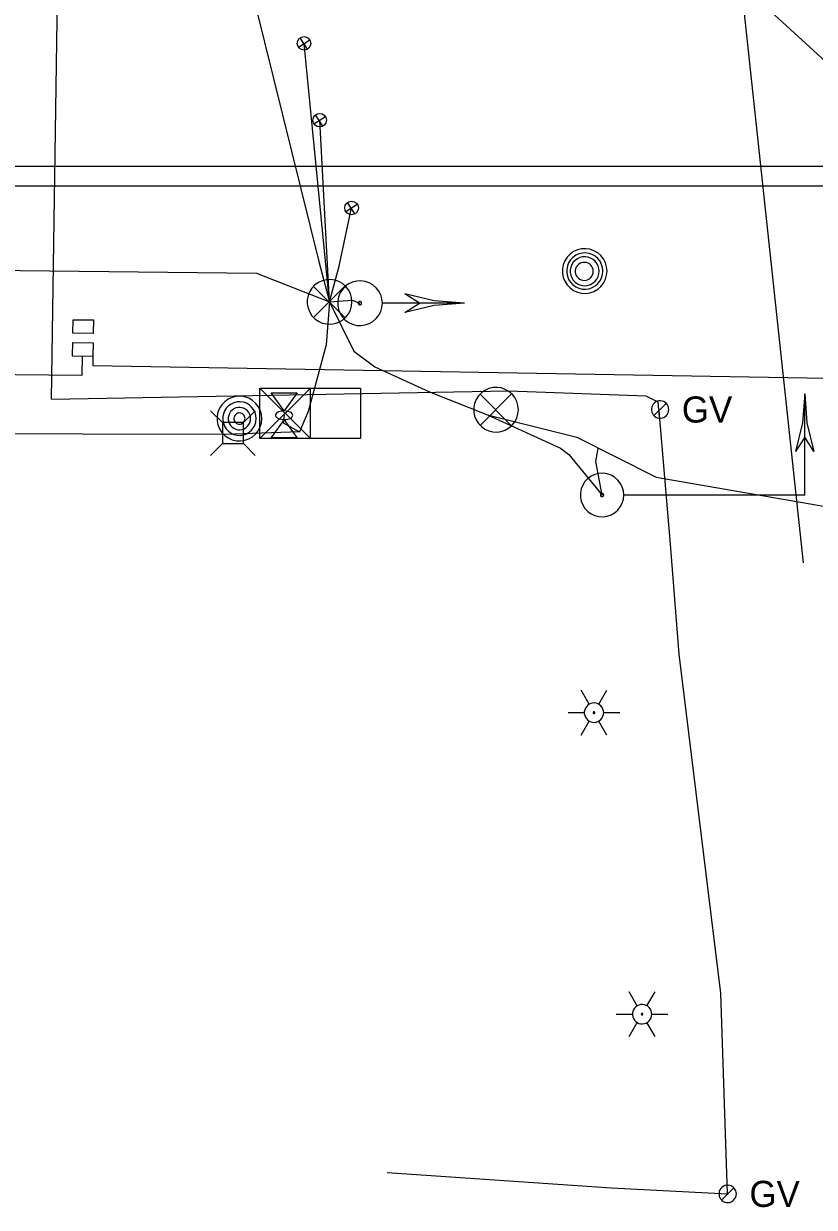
# Model space of a CAD drawing. Extents: x 596028 to 606371, y 330010 to 403088.
# Drawn here: x 604942.5 to 605059.1, y 349725.2 to 349899.9 of the extents above; entities that cross this region are included whole.
import ezdxf

# ---------------------------------------------------------------- set-up
doc = ezdxf.new("R2010")
doc.units = 0
for name, color, linetype in [('E_LTG', 7, 'Continuous'), ('E_SIG', 7, 'Continuous'), ('E_SIG_Conduit', 7, 'Continuous'), ('E_UTL_E', 7, 'Continuous'), ('E_UTL_E_Bold', 7, 'Continuous'), ('E_UTL_E_UG', 7, 'Continuous'), ('E_UTL_FO_UG', 7, 'Continuous'), ('E_UTL_G', 7, 'Continuous'), ('E_UTL_G_UG', 7, 'Continuous'), ('E_UTL_Loop_UG', 7, 'Continuous'), ('E_UTL_MH', 7, 'Continuous'), ('E_UTL_Overhead', 7, 'Continuous'), ('E_UTL_T_UG', 7, 'Continuous')]:
    doc.layers.add(name, color=color, linetype=linetype)

# ---------------------------------------------------------------- blocks, each defined once
blk = doc.blocks.new('_U336')
at = {"layer": 'E_SIG'}
for p, q in [((-6.1, 0.4), (6.1, 0.4)), ((0, 6.1), (0, -6.1))]:
    blk.add_line(p, q, dxfattribs=at)
blk.add_circle((0, 0), 6.1, dxfattribs=at)
blk = doc.blocks.new('_U337')
at = {"layer": 'E_SIG'}
for p, q in [((-6.1, 0.4), (6.1, 0.4)), ((0, 6.1), (0, -6.1))]:
    blk.add_line(p, q, dxfattribs=at)
blk.add_circle((0, 0), 6.1, dxfattribs=at)
blk = doc.blocks.new('_U338')
at = {"layer": 'E_SIG'}
for p, q in [((-6.1, 0.4), (6.1, 0.4)), ((0, 6.1), (0, -6.1))]:
    blk.add_line(p, q, dxfattribs=at)
blk.add_circle((0, 0), 6.1, dxfattribs=at)
blk = doc.blocks.new('ACAD_PROXY_ENTITY_15')
at = {"layer": 'E_LTG'}
for points in [[(1843663.8, 1030159.59), (1843660.17, 1030165.87)], [(1843668.16, 1030159.59), (1843671.79, 1030165.87)], [(1843654.37, 1030155.82), (1843661.62, 1030155.82)], [(1843670.34, 1030155.82), (1843670.26, 1030156.64), (1843670.02, 1030157.44), (1843669.64, 1030158.17), (1843669.13, 1030158.82), (1843668.51, 1030159.36), (1843667.79, 1030159.78), (1843667.01, 1030160.05), (1843666.19, 1030160.17), (1843665.36, 1030160.13), (1843664.56, 1030159.93), (1843663.8, 1030159.59), (1843663.13, 1030159.11), (1843662.56, 1030158.51), (1843662.11, 1030157.81), (1843661.8, 1030157.04), (1843661.64, 1030156.23), (1843661.64, 1030155.4), (1843661.8, 1030154.59), (1843662.11, 1030153.82), (1843662.56, 1030153.12), (1843663.13, 1030152.52), (1843663.8, 1030152.04), (1843664.56, 1030151.7), (1843665.36, 1030151.51), (1843666.19, 1030151.47), (1843667.01, 1030151.58), (1843667.79, 1030151.85), (1843668.51, 1030152.27), (1843669.13, 1030152.81), (1843669.64, 1030153.46), (1843670.02, 1030154.2), (1843670.26, 1030154.99), (1843670.34, 1030155.82)], [(1843670.34, 1030155.82), (1843670.26, 1030156.64), (1843670.02, 1030157.44), (1843669.64, 1030158.17), (1843669.13, 1030158.82), (1843668.51, 1030159.36), (1843667.79, 1030159.78), (1843667.01, 1030160.05), (1843666.19, 1030160.17), (1843665.36, 1030160.13), (1843664.56, 1030159.93), (1843663.8, 1030159.59), (1843663.13, 1030159.11), (1843662.56, 1030158.51), (1843662.11, 1030157.81), (1843661.8, 1030157.04), (1843661.64, 1030156.23), (1843661.64, 1030155.4), (1843661.8, 1030154.59), (1843662.11, 1030153.82), (1843662.56, 1030153.12), (1843663.13, 1030152.52), (1843663.8, 1030152.04), (1843664.56, 1030151.7), (1843665.36, 1030151.51), (1843666.19, 1030151.47), (1843667.01, 1030151.58), (1843667.79, 1030151.85), (1843668.51, 1030152.27), (1843669.13, 1030152.81), (1843669.64, 1030153.46), (1843670.02, 1030154.2), (1843670.26, 1030154.99), (1843670.34, 1030155.82)], [(1843670.34, 1030155.82), (1843670.26, 1030156.64), (1843670.02, 1030157.44), (1843669.64, 1030158.17), (1843669.13, 1030158.82), (1843668.51, 1030159.36), (1843667.79, 1030159.78), (1843667.01, 1030160.05), (1843666.19, 1030160.17), (1843665.36, 1030160.13), (1843664.56, 1030159.93), (1843663.8, 1030159.59), (1843663.13, 1030159.11), (1843662.56, 1030158.51), (1843662.11, 1030157.81), (1843661.8, 1030157.04), (1843661.64, 1030156.23), (1843661.64, 1030155.4), (1843661.8, 1030154.59), (1843662.11, 1030153.82), (1843662.56, 1030153.12), (1843663.13, 1030152.52), (1843663.8, 1030152.04), (1843664.56, 1030151.7), (1843665.36, 1030151.51), (1843666.19, 1030151.47), (1843667.01, 1030151.58), (1843667.79, 1030151.85), (1843668.51, 1030152.27), (1843669.13, 1030152.81), (1843669.64, 1030153.46), (1843670.02, 1030154.2), (1843670.26, 1030154.99), (1843670.34, 1030155.82)], [(1843666.34, 1030155.82), (1843666.34, 1030155.88), (1843666.32, 1030155.95), (1843666.29, 1030156.01), (1843666.24, 1030156.07), (1843666.19, 1030156.11), (1843666.13, 1030156.15), (1843666.07, 1030156.17), (1843666, 1030156.18), (1843665.93, 1030156.18), (1843665.86, 1030156.16), (1843665.8, 1030156.13), (1843665.74, 1030156.09), (1843665.69, 1030156.04), (1843665.66, 1030155.98), (1843665.63, 1030155.92), (1843665.62, 1030155.85), (1843665.62, 1030155.78), (1843665.63, 1030155.71), (1843665.66, 1030155.65), (1843665.69, 1030155.59), (1843665.74, 1030155.54), (1843665.8, 1030155.5), (1843665.86, 1030155.47), (1843665.93, 1030155.46), (1843666, 1030155.45), (1843666.07, 1030155.46), (1843666.13, 1030155.49), (1843666.19, 1030155.52), (1843666.24, 1030155.57), (1843666.29, 1030155.62), (1843666.32, 1030155.68), (1843666.34, 1030155.75), (1843666.34, 1030155.82)], [(1843670.34, 1030155.82), (1843677.59, 1030155.82)], [(1843660.17, 1030145.76), (1843663.8, 1030152.04)], [(1843671.79, 1030145.76), (1843668.16, 1030152.04)]]:
    blk.add_lwpolyline(points, dxfattribs=at)

msp = doc.modelspace()

# ---------------------------------------------------------------- linework, layer by layer
at = {"layer": 'E_SIG'}
for points in [[(604990.87, 349858.81), (604990.81, 349859.44), (604990.64, 349860.04), (604990.35, 349860.6), (604989.96, 349861.09), (604989.49, 349861.5), (604988.94, 349861.81), (604988.35, 349862.02), (604987.73, 349862.11), (604987.1, 349862.08), (604986.49, 349861.93), (604985.92, 349861.67), (604985.41, 349861.31), (604984.98, 349860.85), (604984.64, 349860.32), (604984.41, 349859.74), (604984.29, 349859.13), (604984.29, 349858.5), (604984.41, 349857.88), (604984.64, 349857.3), (604984.98, 349856.77), (604985.41, 349856.32), (604985.92, 349855.95), (604986.49, 349855.69), (604987.1, 349855.55), (604987.73, 349855.52), (604988.35, 349855.61), (604988.94, 349855.81), (604989.49, 349856.12), (604989.96, 349856.54), (604990.35, 349857.03), (604990.64, 349857.59), (604990.81, 349858.19), (604990.87, 349858.81)], [(604989.83, 349861.15), (604985.22, 349856.49)], [(604985.22, 349861.1), (604989.88, 349856.45)], [(604995.36, 349858.62), (604995.3, 349859.24), (604995.12, 349859.85), (604994.83, 349860.4), (604994.44, 349860.9), (604993.97, 349861.31), (604993.43, 349861.62), (604992.83, 349861.83), (604992.21, 349861.92), (604991.59, 349861.89), (604990.98, 349861.74), (604990.41, 349861.48), (604989.89, 349861.11), (604989.46, 349860.66), (604989.12, 349860.13), (604988.89, 349859.55), (604988.77, 349858.93), (604988.77, 349858.31), (604988.89, 349857.69), (604989.12, 349857.11), (604989.46, 349856.58), (604989.89, 349856.13), (604990.41, 349855.76), (604990.98, 349855.5), (604991.59, 349855.35), (604992.21, 349855.32), (604992.83, 349855.41), (604993.43, 349855.62), (604993.97, 349855.93), (604994.44, 349856.34), (604994.83, 349856.84), (604995.12, 349857.39), (604995.3, 349858), (604995.36, 349858.62)], [(604992.31, 349858.62), (604992.3, 349858.67), (604992.29, 349858.71), (604992.27, 349858.76), (604992.24, 349858.79), (604992.2, 349858.83), (604992.16, 349858.85), (604992.12, 349858.87), (604992.07, 349858.87), (604992.02, 349858.87), (604991.97, 349858.86), (604991.93, 349858.84), (604991.89, 349858.81), (604991.86, 349858.78), (604991.83, 349858.74), (604991.81, 349858.69), (604991.8, 349858.64), (604991.8, 349858.6), (604991.81, 349858.55), (604991.83, 349858.5), (604991.86, 349858.46), (604991.89, 349858.43), (604991.93, 349858.4), (604991.97, 349858.38), (604992.02, 349858.37), (604992.07, 349858.37), (604992.12, 349858.37), (604992.16, 349858.39), (604992.2, 349858.41), (604992.24, 349858.45), (604992.27, 349858.48), (604992.29, 349858.53), (604992.3, 349858.57), (604992.31, 349858.62)], [(605000.86, 349858.62), (604998.66, 349860)], [(605007.46, 349858.62), (605003, 349858.97), (604998.66, 349859.99)], [(605007.46, 349858.62), (604995.41, 349858.62)], [(605007.46, 349858.62), (605003, 349858.27), (604998.66, 349857.24)], [(604998.66, 349857.25), (605000.86, 349858.62)], [(604977.58, 349841.6), (604977.52, 349842.22), (604977.34, 349842.82), (604977.06, 349843.38), (604976.67, 349843.87), (604976.19, 349844.28), (604975.65, 349844.6), (604975.06, 349844.8), (604974.44, 349844.89), (604973.81, 349844.86), (604973.2, 349844.71), (604972.63, 349844.45), (604972.12, 349844.09), (604971.69, 349843.64), (604971.35, 349843.11), (604971.11, 349842.53), (604970.99, 349841.91), (604970.99, 349841.28), (604971.11, 349840.67), (604971.35, 349840.08), (604971.69, 349839.56), (604972.12, 349839.1), (604972.63, 349838.74), (604973.2, 349838.48), (604973.81, 349838.33), (604974.44, 349838.3), (604975.06, 349838.39), (604975.65, 349838.59), (604976.19, 349838.91), (604976.67, 349839.32), (604977.06, 349839.81), (604977.34, 349840.37), (604977.52, 349840.97), (604977.58, 349841.6)], [(604977.31, 349838.66), (604977.31, 349846.09)], [(604977.31, 349846.09), (604992.16, 349846.09)], [(604984.74, 349846.09), (604977.31, 349838.66)], [(604977.31, 349846.09), (604984.74, 349838.66)], [(604984.74, 349838.66), (604984.74, 349846.09)], [(604992.16, 349846.09), (604992.16, 349838.66)], [(605015.43, 349842.9), (605015.37, 349843.53), (605015.19, 349844.13), (605014.91, 349844.69), (605014.52, 349845.18), (605014.04, 349845.59), (605013.5, 349845.91), (605012.91, 349846.11), (605012.29, 349846.2), (605011.66, 349846.17), (605011.05, 349846.02), (605010.48, 349845.76), (605009.97, 349845.4), (605009.53, 349844.94), (605009.2, 349844.42), (605008.96, 349843.83), (605008.84, 349843.22), (605008.84, 349842.59), (605008.96, 349841.97), (605009.2, 349841.39), (605009.53, 349840.86), (605009.97, 349840.41), (605010.48, 349840.05), (605011.05, 349839.79), (605011.66, 349839.64), (605012.29, 349839.61), (605012.91, 349839.7), (605013.5, 349839.9), (605014.04, 349840.22), (605014.52, 349840.63), (605014.91, 349841.12), (605015.19, 349841.68), (605015.37, 349842.28), (605015.43, 349842.9)], [(605014.39, 349845.24), (605009.78, 349840.58)], [(605009.78, 349845.19), (605014.43, 349840.54)], [(605057.66, 349845.27), (605057.33, 349840.95), (605056.33, 349836.73)], [(605057.66, 349830.32), (605057.66, 349845.27)], [(605057.66, 349845.27), (605058, 349840.95), (605059, 349836.73)], [(604976.75, 349841.6), (604976.71, 349842.06), (604976.58, 349842.52), (604976.36, 349842.93), (604976.07, 349843.3), (604975.72, 349843.61), (604975.31, 349843.85), (604974.86, 349844), (604974.4, 349844.07), (604973.93, 349844.05), (604973.47, 349843.94), (604973.04, 349843.74), (604972.66, 349843.47), (604972.33, 349843.13), (604972.08, 349842.73), (604971.91, 349842.29), (604971.82, 349841.83), (604971.82, 349841.36), (604971.91, 349840.9), (604972.08, 349840.46), (604972.33, 349840.07), (604972.66, 349839.73), (604973.04, 349839.45), (604973.47, 349839.26), (604973.93, 349839.15), (604974.4, 349839.12), (604974.86, 349839.19), (604975.31, 349839.34), (604975.72, 349839.58), (604976.07, 349839.89), (604976.36, 349840.26), (604976.58, 349840.68), (604976.71, 349841.13), (604976.75, 349841.6)], [(604975.93, 349841.6), (604975.9, 349841.91), (604975.81, 349842.21), (604975.67, 349842.49), (604975.47, 349842.73), (604975.24, 349842.94), (604974.97, 349843.1), (604974.67, 349843.2), (604974.36, 349843.24), (604974.05, 349843.23), (604973.74, 349843.16), (604973.45, 349843.03), (604973.2, 349842.84), (604972.98, 349842.62), (604972.81, 349842.35), (604972.7, 349842.06), (604972.64, 349841.75), (604972.64, 349841.44), (604972.7, 349841.13), (604972.81, 349840.84), (604972.98, 349840.58), (604973.2, 349840.35), (604973.45, 349840.17), (604973.74, 349840.04), (604974.05, 349839.96), (604974.36, 349839.95), (604974.67, 349839.99), (604974.97, 349840.1), (604975.24, 349840.25), (604975.47, 349840.46), (604975.67, 349840.7), (604975.81, 349840.98), (604975.9, 349841.28), (604975.93, 349841.6)], [(604975.1, 349841.6), (604975.09, 349841.75), (604975.05, 349841.9), (604974.97, 349842.04), (604974.88, 349842.17), (604974.76, 349842.27), (604974.62, 349842.35), (604974.47, 349842.4), (604974.32, 349842.42), (604974.16, 349842.41), (604974.01, 349842.38), (604973.87, 349842.31), (604973.74, 349842.22), (604973.63, 349842.11), (604973.55, 349841.97), (604973.49, 349841.83), (604973.46, 349841.67), (604973.46, 349841.52), (604973.49, 349841.36), (604973.55, 349841.22), (604973.63, 349841.09), (604973.74, 349840.97), (604973.87, 349840.88), (604974.01, 349840.82), (604974.16, 349840.78), (604974.32, 349840.77), (604974.47, 349840.79), (604974.62, 349840.85), (604974.76, 349840.92), (604974.88, 349841.03), (604974.97, 349841.15), (604975.05, 349841.29), (604975.09, 349841.44), (604975.1, 349841.6)], [(604984.74, 349842.38), (604984.74, 349842.38)], [(604992.16, 349838.66), (604977.31, 349838.66)], [(605057.66, 349838.86), (605056.33, 349836.73)], [(605059, 349836.73), (605057.66, 349838.86)], [(605030.97, 349830.32), (605030.91, 349830.93), (605030.74, 349831.51), (605030.46, 349832.05), (605030.09, 349832.53), (605029.63, 349832.93), (605029.1, 349833.24), (605028.52, 349833.43), (605027.92, 349833.52), (605027.31, 349833.49), (605026.72, 349833.35), (605026.17, 349833.1), (605025.67, 349832.74), (605025.25, 349832.3), (605024.92, 349831.79), (605024.7, 349831.22), (605024.58, 349830.63), (605024.58, 349830.02), (605024.7, 349829.42), (605024.92, 349828.85), (605025.25, 349828.34), (605025.67, 349827.9), (605026.17, 349827.55), (605026.72, 349827.3), (605027.31, 349827.15), (605027.92, 349827.12), (605028.52, 349827.21), (605029.1, 349827.41), (605029.63, 349827.71), (605030.09, 349828.11), (605030.46, 349828.59), (605030.74, 349829.13), (605030.91, 349829.72), (605030.97, 349830.32)], [(605028.01, 349830.32), (605028.01, 349830.37), (605028, 349830.41), (605027.98, 349830.45), (605027.95, 349830.49), (605027.91, 349830.52), (605027.87, 349830.54), (605027.83, 349830.56), (605027.78, 349830.57), (605027.73, 349830.56), (605027.69, 349830.55), (605027.65, 349830.53), (605027.61, 349830.51), (605027.58, 349830.47), (605027.55, 349830.43), (605027.53, 349830.39), (605027.53, 349830.35), (605027.53, 349830.3), (605027.53, 349830.25), (605027.55, 349830.21), (605027.58, 349830.17), (605027.61, 349830.14), (605027.65, 349830.11), (605027.69, 349830.09), (605027.73, 349830.08), (605027.78, 349830.08), (605027.83, 349830.08), (605027.87, 349830.1), (605027.91, 349830.12), (605027.95, 349830.15), (605027.98, 349830.19), (605028, 349830.23), (605028.01, 349830.28), (605028.01, 349830.32)], [(605057.66, 349830.32), (605031.03, 349830.32)], [(605050.19, 349830.32), (605050.19, 349830.32)]]:
    msp.add_lwpolyline(points, dxfattribs=at)
at = {"layer": 'E_SIG_Conduit'}
for points in [[(604969.92, 349929.73), (604985.98, 349864.78), (604987.57, 349858.81)], [(604741.42, 349865.71), (604976.78, 349863.03)], [(604976.78, 349863.03), (604987.57, 349858.81), (604990.92, 349859.08), (604992.06, 349858.62)], [(604987.57, 349858.81), (604987.07, 349852.47), (604984.41, 349842.64), (604983.14, 349839.65)], [(604987.57, 349858.81), (604991.15, 349851.56), (604994.26, 349849.24), (605002.31, 349845.56), (605010.87, 349842.14), (605024.06, 349838.86), (605035.73, 349832.96), (605069.52, 349827.11), (605072.1, 349826.97), (605134.18, 349822.56), (605136.25, 349822.64)], [(605010.87, 349842.14), (605021.65, 349837.24), (605022.86, 349836.32), (605027.77, 349830.32)], [(605027.77, 349830.32), (605026.86, 349835.29), (605027.19, 349837.2)]]:
    msp.add_lwpolyline(points, dxfattribs=at)
at = {"layer": 'E_UTL_E'}
for points in [[(604971.76, 349841), (604970.01, 349842.75)], [(604974.86, 349841), (604976.61, 349842.75)], [(604974.86, 349841), (604971.76, 349841)], [(604971.76, 349841), (604971.76, 349837.9)], [(604974.86, 349837.9), (604974.86, 349841)], [(604971.76, 349837.9), (604970.01, 349836.15)], [(604971.76, 349837.9), (604974.86, 349837.9)], [(604974.86, 349837.9), (604976.61, 349836.15)]]:
    msp.add_lwpolyline(points, dxfattribs=at)
at = {"layer": 'E_UTL_E_Bold'}
for points in [[(604978.97, 349845.39), (604982.78, 349845.39)], [(604980.88, 349842.72), (604978.97, 349845.39)], [(604982.78, 349845.39), (604980.88, 349842.72)], [(604980.88, 349841.45), (604978.97, 349838.79)], [(604982.15, 349842.09), (604982.12, 349842.21), (604982.05, 349842.32), (604981.94, 349842.43), (604981.79, 349842.52), (604981.61, 349842.6), (604981.4, 349842.66), (604981.17, 349842.7), (604980.94, 349842.72), (604980.69, 349842.71), (604980.46, 349842.69), (604980.24, 349842.64), (604980.04, 349842.57), (604979.88, 349842.48), (604979.75, 349842.38), (604979.66, 349842.26), (604979.61, 349842.15), (604979.61, 349842.02), (604979.66, 349841.91), (604979.75, 349841.79), (604979.88, 349841.69), (604980.04, 349841.61), (604980.24, 349841.54), (604980.46, 349841.49), (604980.69, 349841.46), (604980.94, 349841.45), (604981.17, 349841.47), (604981.4, 349841.51), (604981.61, 349841.57), (604981.79, 349841.65), (604981.94, 349841.74), (604982.05, 349841.85), (604982.12, 349841.97), (604982.15, 349842.09)], [(604982.78, 349838.79), (604980.88, 349841.45)], [(604978.97, 349838.79), (604982.78, 349838.79)]]:
    msp.add_lwpolyline(points, dxfattribs=at)
at = {"layer": 'E_UTL_E_UG'}
for points in [[(604980.88, 349842.09), (604980.73, 349840.99), (604983.14, 349839.65), (604973.44, 349839.32)], [(604814.91, 349827.55), (604815.51, 349830.08), (604816.76, 349833.32), (604849.11, 349837.54), (604884.24, 349839.48), (604928.84, 349839.4), (604973.44, 349839.32)]]:
    msp.add_lwpolyline(points, dxfattribs=at)
at = {"layer": 'E_UTL_FO_UG'}
for points in [[(604949.73, 349856.18), (604952.74, 349856.14), (604952.71, 349854.14), (604949.7, 349854.18)], [(604949.68, 349852.82), (604952.69, 349852.77), (604952.65, 349850.77), (604949.64, 349850.82)]]:
    msp.add_lwpolyline(points, close=True, dxfattribs=at)
for points in [[(604642.2, 349851.11), (604951.1, 349847.98), (604951.15, 349850.79)], [(604952.65, 349850.77), (604952.63, 349849.43), (605060.89, 349847.58), (605150.31, 349848.98)]]:
    msp.add_lwpolyline(points, dxfattribs=at)
at = {"layer": 'E_UTL_G'}
for points in [[(605037.61, 349842.94), (605037.59, 349843.18), (605037.52, 349843.41), (605037.41, 349843.63), (605037.26, 349843.82), (605037.07, 349843.98), (605036.86, 349844.1), (605036.63, 349844.18), (605036.39, 349844.22), (605036.15, 349844.21), (605035.91, 349844.15), (605035.69, 349844.05), (605035.49, 349843.91), (605035.32, 349843.73), (605035.19, 349843.52), (605035.1, 349843.3), (605035.05, 349843.06), (605035.05, 349842.81), (605035.1, 349842.57), (605035.19, 349842.35), (605035.32, 349842.14), (605035.49, 349841.97), (605035.69, 349841.82), (605035.91, 349841.72), (605036.15, 349841.67), (605036.39, 349841.65), (605036.63, 349841.69), (605036.86, 349841.77), (605037.07, 349841.89), (605037.26, 349842.05), (605037.41, 349842.24), (605037.52, 349842.46), (605037.59, 349842.69), (605037.61, 349842.94)], [(605035.42, 349842.03), (605037.24, 349843.84)], [(605047.59, 349727.22), (605047.56, 349727.47), (605047.5, 349727.7), (605047.38, 349727.92), (605047.23, 349728.11), (605047.05, 349728.27), (605046.84, 349728.39), (605046.61, 349728.47), (605046.36, 349728.51), (605046.12, 349728.49), (605045.88, 349728.44), (605045.66, 349728.33), (605045.46, 349728.19), (605045.3, 349728.02), (605045.16, 349727.81), (605045.07, 349727.59), (605045.03, 349727.35), (605045.03, 349727.1), (605045.07, 349726.86), (605045.16, 349726.64), (605045.3, 349726.43), (605045.46, 349726.25), (605045.66, 349726.11), (605045.88, 349726.01), (605046.12, 349725.95), (605046.36, 349725.94), (605046.61, 349725.98), (605046.84, 349726.06), (605047.05, 349726.18), (605047.23, 349726.34), (605047.38, 349726.53), (605047.5, 349726.75), (605047.56, 349726.98), (605047.59, 349727.22)], [(605045.4, 349726.32), (605047.21, 349728.13)]]:
    msp.add_lwpolyline(points, dxfattribs=at)
at = {"layer": 'E_UTL_G_UG'}
msp.add_line((604946.54, 349844.45), (604948.15, 349952.82), dxfattribs=at)
for points in [[(605057.51, 349820.3), (605040.82, 349975.55), (605037.97, 349992.89)], [(604946.54, 349844.45), (605014.04, 349845.69), (605034.23, 349844.97), (605036.01, 349844.09), (605036.2, 349841.8)], [(604996.09, 349730.36), (605029.14, 349728.11), (605046.3, 349727.22), (605045.31, 349756.83), (605039.16, 349806.86), (605037.85, 349823.07), (605036.21, 349842.73)]]:
    msp.add_lwpolyline(points, dxfattribs=at)
at = {"layer": 'E_UTL_Loop_UG'}
for points in [[(604987.57, 349858.81), (604983.81, 349896.95)], [(604987.57, 349858.81), (604986.12, 349885.62)], [(604987.57, 349858.81), (604988.97, 349864.07), (604990.82, 349872.67)]]:
    msp.add_lwpolyline(points, dxfattribs=at)
at = {"layer": 'E_UTL_MH'}
for points in [[(605028.51, 349863.36), (605028.45, 349863.99), (605028.28, 349864.59), (605027.99, 349865.15), (605027.6, 349865.64), (605027.13, 349866.05), (605026.58, 349866.36), (605025.99, 349866.57), (605025.37, 349866.66), (605024.74, 349866.63), (605024.13, 349866.48), (605023.56, 349866.22), (605023.05, 349865.86), (605022.62, 349865.4), (605022.28, 349864.87), (605022.05, 349864.29), (605021.93, 349863.68), (605021.93, 349863.05), (605022.05, 349862.43), (605022.28, 349861.85), (605022.62, 349861.32), (605023.05, 349860.87), (605023.56, 349860.5), (605024.13, 349860.24), (605024.74, 349860.1), (605025.37, 349860.07), (605025.99, 349860.16), (605026.58, 349860.36), (605027.13, 349860.67), (605027.6, 349861.09), (605027.99, 349861.58), (605028.28, 349862.14), (605028.45, 349862.74), (605028.51, 349863.36)], [(605027.9, 349863.36), (605027.85, 349863.86), (605027.71, 349864.35), (605027.47, 349864.81), (605027.16, 349865.21), (605026.77, 349865.54), (605026.33, 349865.79), (605025.85, 349865.96), (605025.35, 349866.03), (605024.84, 349866.01), (605024.35, 349865.89), (605023.88, 349865.68), (605023.47, 349865.38), (605023.12, 349865.01), (605022.84, 349864.58), (605022.65, 349864.11), (605022.56, 349863.61), (605022.56, 349863.1), (605022.65, 349862.6), (605022.84, 349862.13), (605023.12, 349861.7), (605023.47, 349861.34), (605023.88, 349861.04), (605024.35, 349860.83), (605024.84, 349860.71), (605025.35, 349860.68), (605025.85, 349860.76), (605026.33, 349860.92), (605026.77, 349861.18), (605027.16, 349861.51), (605027.47, 349861.91), (605027.71, 349862.36), (605027.85, 349862.85), (605027.9, 349863.36)], [(605027.34, 349863.33), (605027.3, 349863.73), (605027.18, 349864.12), (605027, 349864.48), (605026.75, 349864.8), (605026.44, 349865.06), (605026.09, 349865.27), (605025.71, 349865.4), (605025.31, 349865.46), (605024.9, 349865.44), (605024.51, 349865.34), (605024.14, 349865.17), (605023.81, 349864.94), (605023.53, 349864.65), (605023.31, 349864.31), (605023.16, 349863.93), (605023.09, 349863.53), (605023.09, 349863.13), (605023.16, 349862.73), (605023.31, 349862.35), (605023.53, 349862.01), (605023.81, 349861.72), (605024.14, 349861.49), (605024.51, 349861.32), (605024.9, 349861.22), (605025.31, 349861.2), (605025.71, 349861.26), (605026.09, 349861.39), (605026.44, 349861.6), (605026.75, 349861.86), (605027, 349862.18), (605027.18, 349862.54), (605027.3, 349862.93), (605027.34, 349863.33)], [(605026.48, 349863.31), (605026.46, 349863.57), (605026.38, 349863.81), (605026.27, 349864.03), (605026.11, 349864.23), (605025.92, 349864.4), (605025.7, 349864.53), (605025.46, 349864.61), (605025.21, 349864.64), (605024.96, 349864.63), (605024.71, 349864.57), (605024.48, 349864.47), (605024.28, 349864.32), (605024.1, 349864.14), (605023.96, 349863.92), (605023.87, 349863.69), (605023.82, 349863.44), (605023.82, 349863.19), (605023.87, 349862.94), (605023.96, 349862.7), (605024.1, 349862.49), (605024.28, 349862.31), (605024.48, 349862.16), (605024.71, 349862.06), (605024.96, 349862), (605025.21, 349861.98), (605025.46, 349862.02), (605025.7, 349862.1), (605025.92, 349862.23), (605026.11, 349862.39), (605026.27, 349862.59), (605026.38, 349862.82), (605026.46, 349863.06), (605026.48, 349863.31)]]:
    msp.add_lwpolyline(points, dxfattribs=at)
at = {"layer": 'E_UTL_Overhead'}
msp.add_line((604968.54, 349979.07), (605141.52, 349819.92), dxfattribs=at)
at = {"layer": 'E_UTL_T_UG'}
for p, q in [((604990.59, 349878.82), (605131.85, 349878.82)), ((604989.88, 349875.93), (605131.85, 349875.93))]:
    msp.add_line(p, q, dxfattribs=at)
for points in [[(604648.72, 349878.82), (604990.59, 349878.82)], [(604651.26, 349875.93), (604989.88, 349875.93)]]:
    msp.add_lwpolyline(points, dxfattribs=at)

# ---------------------------------------------------------------- block references
at = {"layer": 'E_LTG', "xscale": 0.32808333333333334, "yscale": 0.32808333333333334}
for p in [(150.5, 11821.26), (157.6, 11776.78)]:
    msp.add_blockref('ACAD_PROXY_ENTITY_15', p, dxfattribs=at)
at = {"layer": 'E_SIG_Conduit', "xscale": 0.16404166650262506, "yscale": 0.16404166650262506, "rotation": 122.69997330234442}
for name, p in [('_U337', (604986.12, 349885.62)), ('_U338', (604990.82, 349872.67))]:
    msp.add_blockref(name, p, dxfattribs=at)
at = {"layer": 'E_UTL_Loop_UG', "xscale": 0.16404166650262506, "yscale": 0.16404166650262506, "rotation": 122.69997330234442}
msp.add_blockref('_U336', (604983.81, 349896.95), dxfattribs=at)

# ---------------------------------------------------------------- texts
at = {"layer": 'E_UTL_G'}
for p in [(605039.54, 349841.01), (605049.51, 349725.3)]:
    msp.add_text('GV', height=3.85, dxfattribs=at).set_placement(p)

doc.saveas('drawing.dxf')
